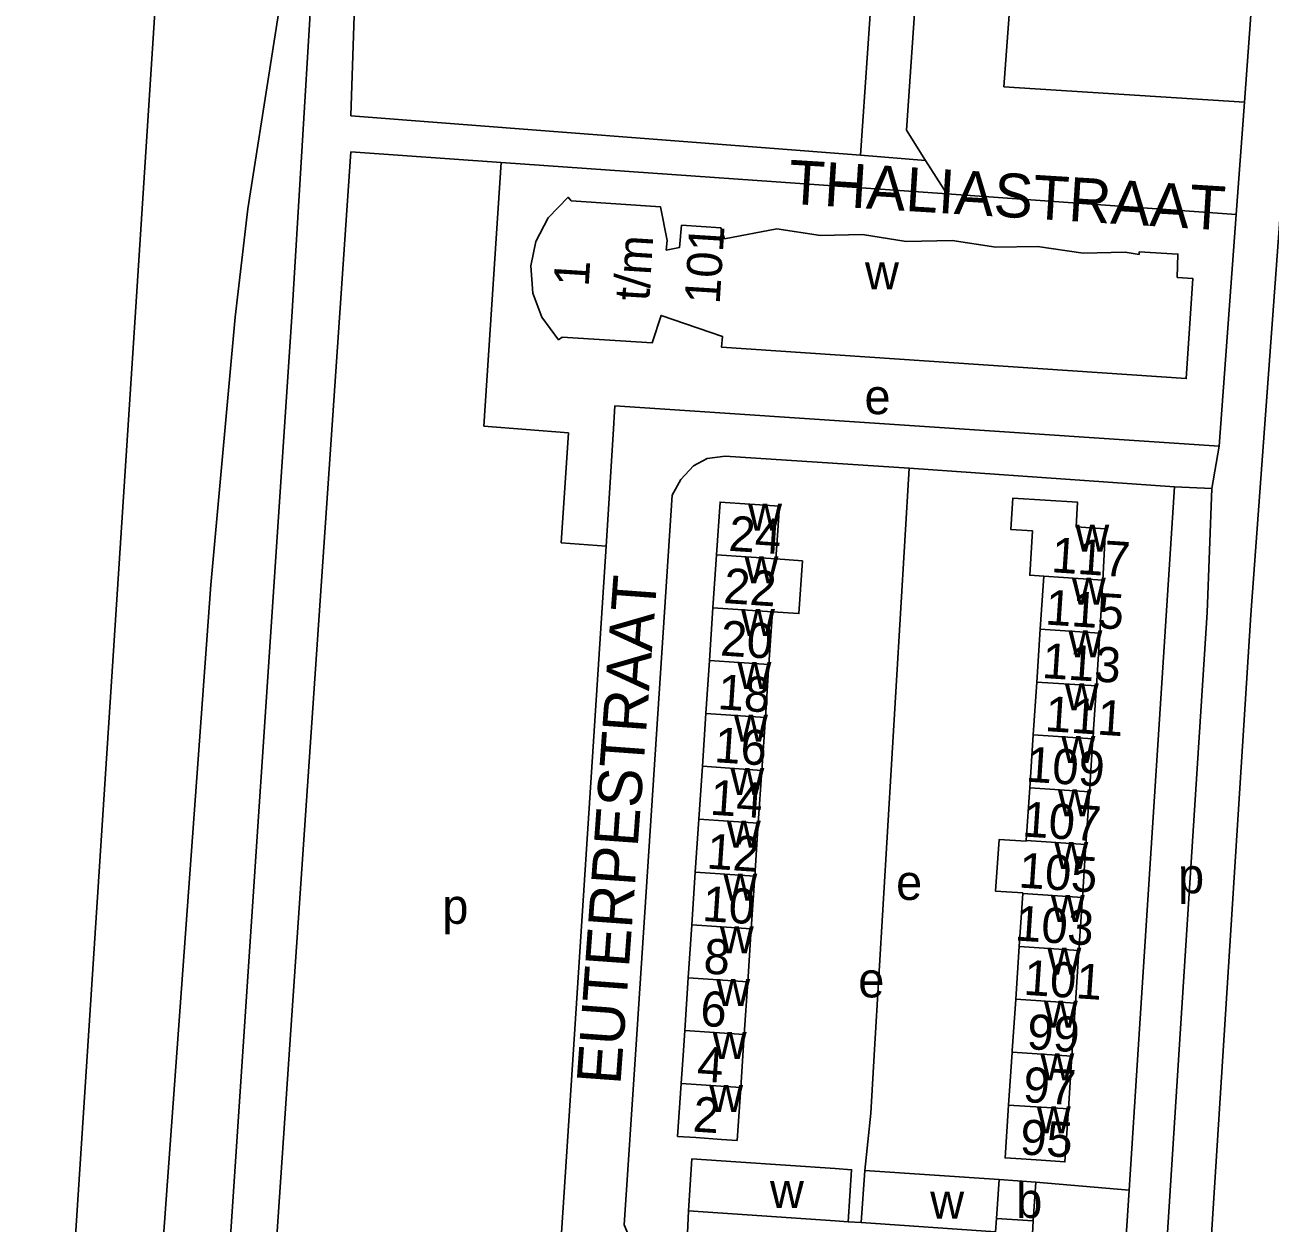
# Model space of a CAD drawing. Extents: x 161773 to 163836, y 384796 to 386521.
# Drawn here: x 161907.8 to 162049.5, y 386146.9 to 386283.2 of the extents above; entities that cross this region are included whole.
import ezdxf

# ---------------------------------------------------------------- set-up
doc = ezdxf.new("R2010")
doc.units = 0
for name, color, linetype in [('BLT_Basislijn', 7, 'Continuous'), ('BLT_Bebouwing', 7, 'Continuous'), ('BLT_Centroide', 7, 'Continuous'), ('BLT_Huisnummer', 7, 'Continuous'), ('BLT_Huisnummer_ tussenligend', 7, 'Continuous'), ('BLT_Huisnummer_reeks', 7, 'Continuous'), ('BLT_Onderverdeling_panden', 7, 'Continuous'), ('BLT_Straatnaam', 7, 'Continuous')]:
    doc.layers.add(name, color=color, linetype=linetype)

msp = doc.modelspace()

# ---------------------------------------------------------------- linework, layer by layer
at = {"layer": 'BLT_Basislijn'}
for p, q in [((162047.33, 386216.15), (162056.95, 386346.98)), ((161923.36, 386296.84), (161920.34, 386250)), ((162020.71, 386296.7), (162019.23, 386276.2)), ((161940.86, 386294.72), (161938.16, 386250.02)), ((162046.61, 386274.46), (162047.33, 386284.36)), ((162019.23, 386276.2), (162046.61, 386274.46)), ((162045.67, 386261.68), (162046.61, 386274.46)), ((161960.02, 386237.6), (161962.01, 386267.59)), ((162012.71, 386264.04), (161962.01, 386267.59)), ((162010.3, 386267.83), (162012.71, 386264.04)), ((162012.71, 386264.04), (162045.67, 386261.68)), ((162043.73, 386235.31), (162045.67, 386261.68)), ((161920.34, 386250), (161913.75, 386148.4)), ((161938.16, 386250.02), (161931.05, 386143.39)), ((161974.75, 386236.64), (161974.95, 386239.9)), ((161973.96, 386223.93), (161974.75, 386236.64)), ((162043.73, 386235.31), (162042.87, 386230.52)), ((162008.45, 386232.82), (162038.65, 386230.71)), ((162038.65, 386230.71), (162042.87, 386230.52)), ((162022.87, 386151.59), (162033.47, 386150.68)), ((161913.75, 386148.4), (161907.79, 386063.87)), ((162001.48, 386147.09), (162002.98, 386146.99))]:
    msp.add_line(p, q, dxfattribs=at)
for points in [[(162017.57, 386431.41), (162018.44, 386428.43), (162015.98, 386385.88), (162008.12, 386271.26), (162010.3, 386267.83)], [(161938.55, 386296.64), (161933.17, 386262.33), (161931.74, 386250)], [(162004.51, 386291.67), (162002.91, 386268.41)], [(162002.91, 386268.41), (161944.89, 386272.91), (161945.47, 386290.03)], [(161962.01, 386267.59), (161944.9, 386268.79), (161937.9, 386166.67), (161936.22, 386142.07), (161968.48, 386140.02)], [(162010.3, 386267.83), (162002.91, 386268.41)], [(161931.74, 386250), (161928.94, 386219.56), (161923.36, 386142.82)], [(161974.95, 386239.9), (162043.73, 386235.31)], [(161969.66, 386236.85), (161960.02, 386237.6)], [(161968.83, 386224.33), (161969.66, 386236.85)], [(162008.45, 386232.82), (161987.5, 386234.17), (161985.43, 386233.93), (161983.9, 386233.09), (161982.46, 386231.53), (161981.45, 386229.73), (161977.31, 386166.67), (161976, 386146.74), (161976.78, 386144.85), (161978.2, 386143.69), (161981.25, 386143.14), (161982.85, 386143.08), (161983.08, 386143.29), (161983.31, 386148.33)], [(162008.45, 386232.82), (162004.49, 386166.67), (162004.06, 386159.45), (162003.39, 386152.93)], [(162038.65, 386230.71), (162034.51, 386166.67), (162033.47, 386150.68)], [(162042.87, 386230.52), (162042.34, 386216.4), (162039.17, 386166.67), (162037.43, 386139.3)], [(161973.96, 386223.93), (161968.83, 386224.33)], [(161973.96, 386223.93), (161970.22, 386166.67), (161968.48, 386140.02)], [(162047.33, 386216.15), (162042.54, 386140.82)], [(162033.47, 386150.68), (162032.76, 386139.64)], [(162022.57, 386147.18), (162022.2, 386140.51), (162032.76, 386139.64)]]:
    msp.add_lwpolyline(points, dxfattribs=at)
at = {"layer": 'BLT_Bebouwing'}
for p, q in [((161986.51, 386222.95), (161986.11, 386216.94)), ((162023.75, 386220.53), (162023.35, 386214.51)), ((162030.15, 386214.06), (162030.49, 386220.08)), ((161986.11, 386216.94), (161985.7, 386210.92)), ((161992.88, 386216.48), (161992.48, 386210.47)), ((162023.35, 386214.51), (162022.95, 386208.49)), ((162029.75, 386208.04), (162030.15, 386214.06)), ((161985.7, 386210.92), (161985.3, 386204.91)), ((161992.48, 386210.47), (161992.07, 386204.46)), ((162022.95, 386208.49), (162022.56, 386202.48)), ((162029.35, 386202.03), (162029.75, 386208.04)), ((161985.3, 386204.91), (161984.9, 386198.9)), ((161992.07, 386204.46), (161991.67, 386198.44)), ((162022.56, 386202.48), (162022.16, 386196.46)), ((162028.95, 386196.01), (162029.35, 386202.03)), ((161984.9, 386198.9), (161984.5, 386192.88)), ((161991.67, 386198.44), (161991.27, 386192.43)), ((162022.16, 386196.46), (162021.76, 386190.45)), ((162028.55, 386190), (162028.95, 386196.01)), ((161984.5, 386192.88), (161984.09, 386186.87)), ((161991.27, 386192.43), (161990.87, 386186.42)), ((162028.15, 386183.98), (162028.55, 386190)), ((161984.09, 386186.87), (161983.69, 386180.86)), ((161990.87, 386186.42), (161990.46, 386180.41)), ((162021.36, 386184.43), (162020.96, 386178.42)), ((162027.76, 386177.96), (162028.15, 386183.98)), ((161983.69, 386180.86), (161983.29, 386174.85)), ((161990.46, 386180.41), (161990.06, 386174.39)), ((162020.96, 386178.42), (162020.56, 386172.4)), ((162027.36, 386171.95), (162027.76, 386177.96)), ((161983.29, 386174.85), (161982.89, 386168.83)), ((161990.06, 386174.39), (161989.66, 386168.38)), ((162020.16, 386166.38), (162019.76, 386160.37)), ((162026.56, 386159.92), (162026.96, 386165.93)), ((161983.31, 386148.33), (161983.71, 386154.25)), ((162002.98, 386146.99), (162003.39, 386152.93)), ((162003.39, 386152.93), (162018.68, 386151.88)), ((162018.68, 386151.88), (162022.87, 386151.59)), ((162022.87, 386151.59), (162022.57, 386147.18)), ((162000, 386147.19), (161983.31, 386148.33)), ((162001.48, 386147.09), (162000, 386147.19)), ((162022.57, 386147.18), (162018.37, 386147.47))]:
    msp.add_line(p, q, dxfattribs=at)
for points in [[(161969.95, 386263.22), (161969.62, 386263.64), (161967.34, 386261.29), (161965.96, 386258.62), (161965.38, 386255.83), (161965.59, 386252.74), (161966.61, 386250), (161968.53, 386247.43), (161968.94, 386247.72)], [(161968.94, 386247.72), (161979.19, 386247.09), (161980.2, 386250.19), (161987.18, 386247.8), (161987.08, 386246.57), (162039.98, 386243), (162040.72, 386254.4), (162038.96, 386254.51), (162039.03, 386257.18), (162034.62, 386257.42), (162034.61, 386257.13), (162033.01, 386257.4), (162028.24, 386257.29), (162023.06, 386258.05), (162018.29, 386257.95), (162013.34, 386258.71), (162008.09, 386258.62), (162003.12, 386259.39), (161998.33, 386259.28), (161993.37, 386260.03), (161987.42, 386258.91), (161987.02, 386260.15), (161982.54, 386260.45), (161982.31, 386257.93), (161980.79, 386257.63), (161980.88, 386258.72), (161980.15, 386262.54), (161969.95, 386263.22)], [(161993.28, 386222.5), (161993.35, 386223.52), (161993.68, 386228.51), (161986.91, 386228.96), (161986.51, 386222.95)], [(162030.49, 386220.08), (162030.78, 386225.92), (162027.43, 386226.14), (162027.61, 386228.94), (162020.24, 386229.41), (162020, 386225.85), (162022.49, 386225.68), (162022.16, 386220.63), (162023.75, 386220.53)], [(161993.28, 386222.5), (161996.28, 386222.27), (161995.88, 386216.28), (161992.88, 386216.48)], [(162021.76, 386190.45), (162021.75, 386190.37), (162018.67, 386190.57), (162018.27, 386184.69), (162021.36, 386184.49), (162021.36, 386184.43)], [(162020.56, 386172.4), (162020.17, 386166.52), (162020.16, 386166.38)], [(162026.96, 386165.93), (162027, 386166.52), (162027.36, 386171.95)], [(161982.89, 386168.83), (161982.74, 386166.57), (161982.49, 386162.82)], [(161989.66, 386168.38), (161989.54, 386166.57), (161989.26, 386162.37)], [(161982.49, 386162.82), (161982.08, 386156.8), (161984.14, 386156.66)], [(161984.14, 386156.66), (161987.07, 386156.46), (161988.86, 386156.35), (161989.26, 386162.37)], [(162019.76, 386160.37), (162019.36, 386154.35), (162021.17, 386154.23), (162023.47, 386154.08)], [(162023.47, 386154.08), (162026.16, 386153.9), (162026.56, 386159.92)], [(161983.71, 386154.25), (161988.7, 386153.91), (162000, 386153.14)], [(162000, 386153.14), (162001.89, 386153.01), (162001.48, 386147.09)], [(162018.37, 386147.47), (162018.27, 386145.93), (162002.98, 386146.99)]]:
    msp.add_lwpolyline(points, dxfattribs=at)
at = {"layer": 'BLT_Onderverdeling_panden'}
for p, q in [((161986.51, 386222.95), (161993.28, 386222.5)), ((162023.75, 386220.53), (162030.49, 386220.08)), ((161986.11, 386216.94), (161992.88, 386216.48)), ((162023.35, 386214.51), (162030.15, 386214.06)), ((161985.7, 386210.92), (161992.48, 386210.47)), ((162022.95, 386208.49), (162029.75, 386208.04)), ((161985.3, 386204.91), (161992.07, 386204.46)), ((162022.56, 386202.48), (162029.35, 386202.03)), ((161984.9, 386198.9), (161991.67, 386198.44)), ((162022.16, 386196.46), (162028.95, 386196.01)), ((161984.5, 386192.88), (161991.27, 386192.43)), ((162021.76, 386190.45), (162028.55, 386190)), ((161984.09, 386186.87), (161990.87, 386186.42)), ((162021.36, 386184.43), (162028.15, 386183.98)), ((161983.69, 386180.86), (161990.46, 386180.41)), ((162020.96, 386178.42), (162027.76, 386177.96)), ((161983.29, 386174.85), (161990.06, 386174.39)), ((162020.56, 386172.4), (162027.36, 386171.95)), ((161982.89, 386168.83), (161989.66, 386168.38)), ((162020.16, 386166.38), (162026.96, 386165.93)), ((161982.49, 386162.82), (161989.26, 386162.37)), ((162019.76, 386160.37), (162026.56, 386159.92)), ((162018.68, 386151.88), (162018.37, 386147.47))]:
    msp.add_line(p, q, dxfattribs=at)

# ---------------------------------------------------------------- texts
at = {"layer": 'BLT_Centroide'}
for s, p in [('w', (162003.41, 386253.16)), ('e', (162003.35, 386238.96)), ('w', (161990.1, 386225.72)), ('w', (162027.35, 386223.32)), ('w', (161989.69, 386219.72)), ('w', (162026.95, 386217.29)), ('w', (161989.29, 386213.72)), ('w', (162026.56, 386211.29)), ('w', (161988.89, 386207.69)), ('w', (162026.15, 386205.26)), ('w', (161988.49, 386201.69)), ('w', (162025.76, 386199.26)), ('w', (161988.08, 386195.65)), ('w', (162025.35, 386193.22)), ('w', (161987.68, 386189.65)), ('w', (162024.96, 386187.22)), ('p', (162039.04, 386184.46)), ('w', (161987.28, 386183.62)), ('e', (162006.95, 386183.7)), ('p', (161955.3, 386180.98)), ('w', (162024.56, 386181.19)), ('w', (161986.88, 386177.62)), ('w', (162024.16, 386175.19)), ('w', (161986.47, 386171.62)), ('e', (162002.64, 386172.61)), ('w', (162023.76, 386169.16)), ('w', (161986.07, 386165.59)), ('w', (162023.36, 386163.16)), ('w', (161985.67, 386159.59)), ('w', (162022.96, 386157.13)), ('w', (161992.59, 386148.66)), ('b', (162020.62, 386147.53)), ('w', (162010.83, 386147.44))]:
    msp.add_text(s, height=4, dxfattribs=at).set_placement(p)
at = {"layer": 'BLT_Huisnummer'}
for s, rotation, p in [('24', 356.1736, (161987.82, 386223.43)), ('117', 356.2033, (162024.54, 386220.99)), ('18', 356.173, (161986.57, 386205.41)), ('111', 356.2033, (162023.82, 386202.92)), ('14', 356.173, (161985.7, 386193.41)), ('107', 356.2027, (162021.24, 386190.93)), ('10', 356.1724, (161984.82, 386181.32)), ('103', 356.2027, (162020.41, 386179.1)), ('6', 356.1724, (161984.58, 386169.39)), ('99', 356.2027, (162021.76, 386166.75)), ('2', 356.1699, (161983.74, 386157.36)), ('95', 356.2007, (162020.98, 386154.77))]:
    msp.add_text(s, height=4, rotation=rotation, dxfattribs=at).set_placement(p)
at = {"layer": 'BLT_Huisnummer_ tussenligend'}
for s, rotation, p in [('22', 356.173, (161987.24, 386217.48)), ('115', 356.2007, (162023.85, 386215.04)), ('20', 356.173, (161986.87, 386211.52)), ('113', 356.2007, (162023.49, 386208.96)), ('16', 356.173, (161986.18, 386199.38)), ('109', 356.2007, (162021.65, 386197.17)), ('12', 356.1724, (161985.31, 386187.28)), ('105', 356.2007, (162020.82, 386185.12)), ('8', 356.1724, (161984.95, 386175.35)), ('101', 356.2007, (162021.39, 386172.92)), ('4', 356.1699, (161984.21, 386163.09)), ('97', 356.2007, (162021.33, 386160.73))]:
    msp.add_text(s, height=4, rotation=rotation, dxfattribs=at).set_placement(p)
at = {"layer": 'BLT_Huisnummer_reeks'}
for s, p in [('101', (161986.86, 386251.4)), ('t/m', (161978.84, 386251.77)), ('1', (161971.95, 386253.4))]:
    msp.add_text(s, height=4, rotation=86.3714, dxfattribs=at).set_placement(p)
at = {"layer": 'BLT_Straatnaam'}
for s, rotation, p in [('THALIASTRAAT', 356.4791, (161994.58, 386262.91)), ('EUTERPESTRAAT', 85.8416, (161975.57, 386162.59))]:
    msp.add_text(s, height=5, rotation=rotation, dxfattribs=at).set_placement(p)

doc.saveas('drawing.dxf')
